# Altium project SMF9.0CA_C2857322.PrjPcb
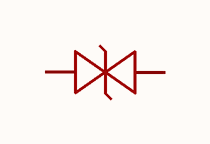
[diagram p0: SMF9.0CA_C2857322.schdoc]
1 sheet, 1 parts. Net scope: global (net labels, ports and power ports of the same name join across sheets).

## Sheet SMF9.0CA_C2857322.schdoc
size 127 x 101 mm

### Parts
D?  smf9.0ca_c2857322  [SMF_L2.9-W1.9-LS3.9-BI]  (value not drawn)

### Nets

Not connected (* = marked no-connect by the designer): D? 1(C) 2(A)

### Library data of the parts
D? = smf9.0ca_c2857322: 极性:双向;反向截止电压(Vrwm):9V;钳位电压:15.4V;峰值脉冲电流(Ipp):13A;峰值脉冲功率(Ppp):200W@10/1000us;击穿电压(VBR):10V;; Manufacturer: JSMSEMI(杰盛微); AddInBom: yes; ModelId: 9b190ad72b2a4f2384918ea07687d3cf; ModelName: DO-219AB_L2.8-W1.8-H1.0-LS3.7; ModelTransform: 145.669,70.866,0,0,0,0,0,0,0; Polarity: 双向; Reverse Stand-Off Voltage (Vrwm): 9V; Clamping Voltage: 15.4V; Peak Pulse Current (Ipp): 13A; Voltage - Breakdown: 10V; Reverse Leakage Current (Ir): 5uA; Number of Channels: 单路; Type: TVS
